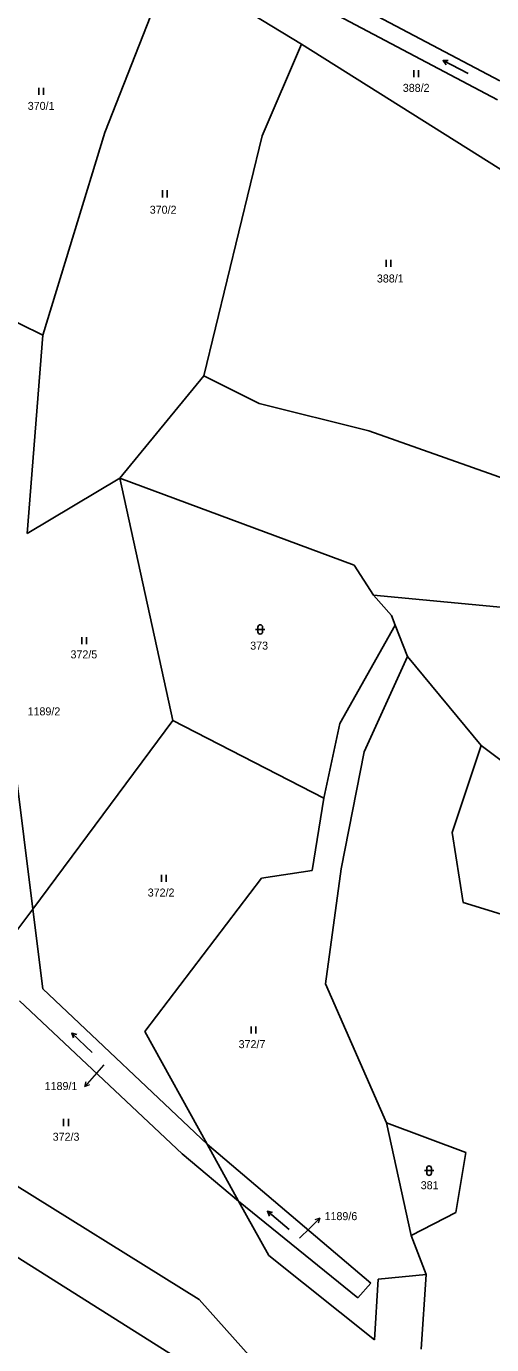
# Model space of a CAD drawing. Extents: x -765428 to -762163, y -1107632 to -1104975.
# Drawn here: x -764351.2 to -764252.2, y -1106880.1 to -1106600.1 of the extents above; entities that cross this region are included whole.
import ezdxf
from ezdxf.enums import TextEntityAlignment as Align

# ---------------------------------------------------------------- set-up
doc = ezdxf.new("R2010")
doc.units = 0
doc.header["$LTSCALE"] = 0.68
for name, color, linetype, lineweight in [('1', 7, 'Continuous', 25), ('3', 7, 'Continuous', 25), ('7', 7, 'Continuous', 13)]:
    doc.layers.add(name, color=color, linetype=linetype, lineweight=lineweight)
doc.layers.add('2', color=7, linetype='Continuous')

msp = doc.modelspace()

# ---------------------------------------------------------------- linework, layer by layer
at = {"layer": '1'}
for p, q in [((-764251.03, -1106615.67), (-764316.87, -1106580.85)), ((-764334.47, -1106622.59), (-764320.52, -1106586.94)), ((-764320.52, -1106586.94), (-764292.69, -1106603.84)), ((-764250.5, -1106611.63), (-764292.59, -1106589.42)), ((-764292.69, -1106603.84), (-764301.04, -1106623.32)), ((-764292.69, -1106603.84), (-764242.78, -1106635.19)), ((-764347.67, -1106665.66), (-764334.47, -1106622.59)), ((-764313.41, -1106674.29), (-764301.04, -1106623.32)), ((-764347.67, -1106665.66), (-764369.78, -1106654.87)), ((-764350.99, -1106707.82), (-764347.67, -1106665.66)), ((-764331.29, -1106696.07), (-764313.41, -1106674.29)), ((-764313.41, -1106674.29), (-764301.7, -1106680.17)), ((-764301.7, -1106680.17), (-764278.35, -1106685.97)), ((-764278.35, -1106685.97), (-764245.35, -1106697.7)), ((-764331.29, -1106696.07), (-764350.99, -1106707.82)), ((-764331.29, -1106696.07), (-764320.01, -1106747.57)), ((-764281.49, -1106714.52), (-764331.29, -1106696.07)), ((-764349.82, -1106787.6), (-764359.7, -1106708.53)), ((-764277.34, -1106720.91), (-764281.49, -1106714.52)), ((-764277.34, -1106720.91), (-764273.56, -1106725.21)), ((-764242.99, -1106724.15), (-764277.34, -1106720.91)), ((-764273.56, -1106725.21), (-764272.77, -1106727.28)), ((-764284.52, -1106748.18), (-764272.77, -1106727.28)), ((-764272.77, -1106727.28), (-764270.14, -1106733.98)), ((-764279.35, -1106754.17), (-764270.14, -1106733.98)), ((-764270.14, -1106733.98), (-764254.49, -1106752.86)), ((-764320.01, -1106747.57), (-764349.82, -1106787.6)), ((-764320.01, -1106747.57), (-764287.92, -1106764.01)), ((-764284.52, -1106748.18), (-764287.92, -1106764.01)), ((-764254.49, -1106752.86), (-764260.64, -1106771.37)), ((-764242.8, -1106761.67), (-764254.49, -1106752.86)), ((-764284.27, -1106779.07), (-764279.35, -1106754.17)), ((-764287.92, -1106764.01), (-764290.44, -1106779.39)), ((-764260.64, -1106771.37), (-764258.31, -1106786.23)), ((-764301.18, -1106781.02), (-764326.02, -1106813.64)), ((-764290.44, -1106779.39), (-764301.18, -1106781.02)), ((-764287.59, -1106803.46), (-764284.27, -1106779.07)), ((-764258.31, -1106786.23), (-764246.51, -1106789.83)), ((-764349.82, -1106787.6), (-764354.27, -1106793.57)), ((-764347.7, -1106804.57), (-764349.82, -1106787.6)), ((-764274.6, -1106833), (-764287.59, -1106803.46)), ((-764347.7, -1106804.57), (-764312.76, -1106837.55)), ((-764352.66, -1106807.09), (-764318.07, -1106839.58)), ((-764326.02, -1106813.64), (-764312.76, -1106837.55)), ((-764420.5, -1106819.24), (-764304.49, -1106892.16)), ((-764314.41, -1106870.55), (-764380.85, -1106829.26)), ((-764274.6, -1106833), (-764269.37, -1106856.93)), ((-764257.7, -1106839.33), (-764274.6, -1106833)), ((-764318.07, -1106839.58), (-764306.04, -1106849.68)), ((-764312.76, -1106837.55), (-764277.91, -1106867.1)), ((-764312.76, -1106837.55), (-764306.04, -1106849.68)), ((-764259.88, -1106852.08), (-764257.7, -1106839.33)), ((-764280.73, -1106870.17), (-764306.04, -1106849.68)), ((-764306.04, -1106849.68), (-764299.64, -1106861.23)), ((-764269.37, -1106856.93), (-764259.88, -1106852.08)), ((-764269.37, -1106856.93), (-764266.15, -1106865.23)), ((-764299.64, -1106861.23), (-764277.15, -1106879.15)), ((-764276.38, -1106866.22), (-764266.15, -1106865.23)), ((-764266.15, -1106865.23), (-764267.24, -1106881.14)), ((-764277.91, -1106867.1), (-764280.73, -1106870.17)), ((-764277.15, -1106879.15), (-764276.38, -1106866.22)), ((-764303.23, -1106883.06), (-764314.41, -1106870.55))]:
    msp.add_line(p, q, dxfattribs=at)
at = {"layer": '3'}
for p, q in [((-764262.574, -1106607.353), (-764261.476, -1106607.349)), ((-764268.801, -1106610.86), (-764268.801, -1106609.36)), ((-764267.8, -1106610.86), (-764267.8, -1106609.36)), ((-764348.551, -1106614.61), (-764348.551, -1106613.11)), ((-764347.55, -1106614.61), (-764347.55, -1106613.11)), ((-764322.241, -1106636.4), (-764322.241, -1106634.9)), ((-764321.24, -1106636.4), (-764321.24, -1106634.9)), ((-764274.651, -1106651.14), (-764274.651, -1106649.64)), ((-764273.65, -1106651.14), (-764273.65, -1106649.64)), ((-764302.461, -1106728.191), (-764300.459, -1106728.191)), ((-764301.961, -1106727.691), (-764301.961, -1106728.692)), ((-764300.959, -1106728.692), (-764300.959, -1106727.691)), ((-764339.391, -1106731.34), (-764339.391, -1106729.84)), ((-764338.39, -1106731.34), (-764338.39, -1106729.84)), ((-764322.461, -1106781.8), (-764322.461, -1106780.3)), ((-764321.46, -1106781.8), (-764321.46, -1106780.3)), ((-764341.494, -1106813.938), (-764340.443, -1106814.256)), ((-764303.381, -1106814.03), (-764303.381, -1106812.53)), ((-764302.38, -1106814.03), (-764302.38, -1106812.53)), ((-764343.251, -1106833.7), (-764343.251, -1106832.2)), ((-764342.25, -1106833.7), (-764342.25, -1106832.2)), ((-764266.051, -1106842.681), (-764266.051, -1106843.682)), ((-764265.049, -1106843.682), (-764265.049, -1106842.681)), ((-764266.551, -1106843.181), (-764264.549, -1106843.181)), ((-764299.916, -1106851.824), (-764298.845, -1106852.068))]:
    msp.add_line(p, q, dxfattribs=at)
for points in [[(-764257.228, -1106610.077), (-764262.574, -1106607.353), (-764261.931, -1106608.243)], [(-764337.178, -1106818.106), (-764341.494, -1106813.938), (-764341.14, -1106814.977)], [(-764295.319, -1106855.681), (-764299.916, -1106851.824), (-764299.49, -1106852.836)]]:
    msp.add_lwpolyline(points, dxfattribs=at)
for centre, start, end in [((-764301.46, -1106727.6909), 0, 180), ((-764301.46, -1106728.6909), 180, 359.98789), ((-764265.55, -1106842.6809), 0, 180), ((-764265.55, -1106843.6809), 180, 359.98789)]:
    msp.add_arc(centre, 0.5, start, end, dxfattribs=at)
at = {"layer": '7'}
for p, q in [((-764338.739, -1106825.335), (-764337.704, -1106824.908)), ((-764288.778, -1106853.258), (-764289.84, -1106853.612))]:
    msp.add_line(p, q, dxfattribs=at)
for points in [[(-764334.74, -1106820.73), (-764336.77, -1106823.07), (-764338.739, -1106825.335), (-764338.46, -1106824.251)], [(-764293.08, -1106857.54), (-764290.9, -1106855.38), (-764288.778, -1106853.258), (-764289.132, -1106854.32)]]:
    msp.add_lwpolyline(points, dxfattribs=at)

# ---------------------------------------------------------------- texts
at = {"layer": '2'}
for s, p in [('388/2', (-764268.29, -1106613.985)), ('370/1', (-764348.04, -1106617.815)), ('370/2', (-764322.1, -1106639.875)), ('388/1', (-764273.8, -1106654.485)), ('372/5', (-764338.95, -1106734.345)), ('372/2', (-764322.53, -1106784.945)), ('372/7', (-764303.2, -1106817.155)), ('372/3', (-764342.74, -1106836.825))]:
    msp.add_text(s, height=1.7, dxfattribs=at).set_placement(p, align=Align.CENTER)
for s, p in [('373', (-764303.58, -1106732.485)), ('1189/2', (-764350.92, -1106746.455)), ('381', (-764267.32, -1106847.125)), ('1189/6', (-764287.77, -1106853.695))]:
    msp.add_text(s, height=1.7, dxfattribs=at).set_placement(p)
msp.add_text('1189/1', height=1.7, dxfattribs=at).set_placement((-764340.339, -1106826.055), align=Align.RIGHT)

doc.saveas('drawing.dxf')
